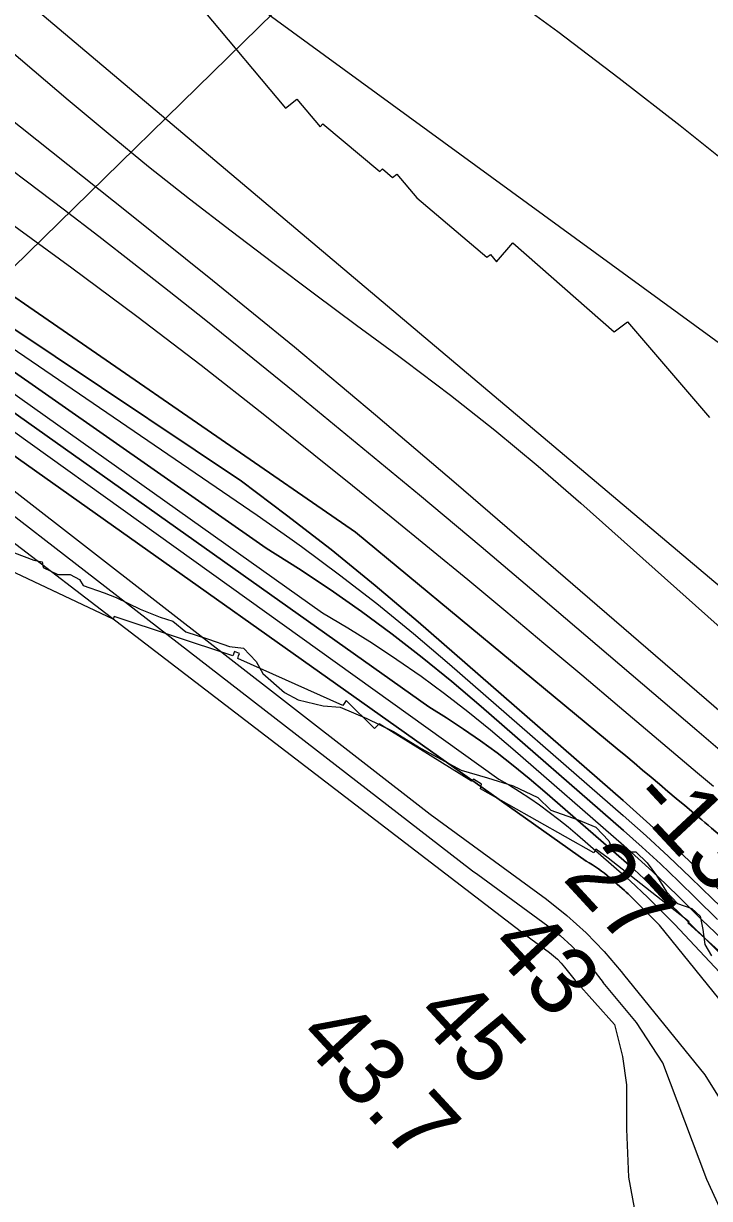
# Model space of a CAD drawing. Extents: x 3172231 to 3210228, y 940198 to 965780.
# Drawn here: x 3191420 to 3192098, y 946666 to 947827 of the extents above; entities that cross this region are included whole.
import ezdxf

# ---------------------------------------------------------------- set-up
doc = ezdxf.new("R2010")
doc.units = 0
for name, color, linetype in [('V-RIVR-EDGE', 7, 'Continuous'), ('V-RIVR-RANG', 7, 'Continuous'), ('V-RRAP-RVMT', 7, 'Continuous'), ('V-TOPO-DPTH', 7, 'Continuous'), ('V-TOPO-MAJR', 7, 'Continuous'), ('V-TOPO-MINR', 7, 'Continuous'), ('V-TOPO-WATR', 7, 'Continuous')]:
    doc.layers.add(name, color=color, linetype=linetype)

msp = doc.modelspace()

# ---------------------------------------------------------------- linework, layer by layer
at = {"layer": 'V-RIVR-EDGE'}
for points in [[(3191410.989, 947304.007), (3191430.16, 947296.699), (3191438.454, 947295.123), (3191439.477, 947289.415), (3191453.982, 947282.637), (3191465.91, 947282.608), (3191475.232, 947277.399), (3191478.848, 947271.685), (3191499.575, 947264.373), (3191511.492, 947259.676), (3191535.32, 947248.207), (3191555.009, 947240.379), (3191567.445, 947236.199), (3191580.385, 947225.795), (3191602.668, 947218.479), (3191623.395, 947211.167), (3191637.393, 947209.577)], [(3191637.393, 947209.577), (3191649.808, 947196.58), (3191656.521, 947184.635), (3191677.738, 947165.913), (3191691.204, 947158.619), (3191716.084, 947152.852), (3191732.676, 947151.255), (3191759.099, 947140.299), (3191785.516, 947127.268), (3191812.962, 947110.604), (3191852.324, 947089.243), (3191878.236, 947081.4), (3191903.629, 947073.558), (3191927.976, 947062.088), (3191940.911, 947049.609), (3191967.856, 947040.207), (3191985.471, 947032.903), (3191998.403, 947019.387), (3192001.494, 947011.081), (3192013.416, 947008.458), (3192024.826, 947008.43), (3192036.209, 946997.511), (3192045.513, 946985.041), (3192055.327, 946968.94), (3192066.19, 946957.503), (3192080.18, 946952.282), (3192088.46, 946945.001), (3192091.019, 946931.51), (3192093.058, 946916.984), (3192099.772, 946905.558)]]:
    msp.add_lwpolyline(points, dxfattribs=at)
at = {"layer": 'V-RIVR-RANG'}
msp.add_line((3190962.933, 947149.209), (3191771.579, 947939.938), dxfattribs=at)
at = {"layer": 'V-RRAP-RVMT'}
for p, q in [((3191598.117, 947839.368), (3191678.924, 947743.409)), ((3191678.924, 947743.409), (3191690.144, 947752.294)), ((3191690.144, 947752.294), (3191713.026, 947724.749)), ((3191713.026, 947724.749), (3191715.597, 947727.872)), ((3191715.597, 947727.872), (3191772.016, 947680.848)), ((3191772.016, 947680.848), (3191774.569, 947683.416)), ((3191774.569, 947683.416), (3191784.622, 947674.912)), ((3191784.622, 947674.912), (3191788.771, 947678.215)), ((3191788.771, 947678.215), (3191808.451, 947654.756)), ((3191808.451, 947654.756), (3191877.73, 947596.155)), ((3191887.379, 947591.567), (3191903.504, 947610.203)), ((3191903.504, 947610.203), (3192003.597, 947522.334)), ((3191877.73, 947596.155), (3191881.207, 947598.794)), ((3191881.207, 947598.794), (3191887.379, 947591.567)), ((3192003.597, 947522.334), (3192016.837, 947532.321)), ((3192016.837, 947532.321), (3192097.733, 947437.716)), ((3191508.358, 947238.465), (3191379.902, 947299.004)), ((3191509.476, 947241.033), (3191508.358, 947238.465)), ((3191626.634, 947202.077), (3191509.476, 947241.033)), ((3191628.502, 947206.514), (3191626.634, 947202.077)), ((3191633.347, 947204.462), (3191628.502, 947206.514)), ((3191631.761, 947199.489), (3191632.348, 947202.01)), ((3191632.348, 947202.01), (3191633.347, 947204.462)), ((3191735.368, 947152.878), (3191631.761, 947199.489)), ((3191738.606, 947157.933), (3191735.368, 947152.878)), ((3191766.795, 947130.142), (3191738.606, 947157.933)), ((3191771.263, 947134.875), (3191766.795, 947130.142)), ((3191862.56, 947078.107), (3191771.263, 947134.875)), ((3191864.608, 947080.065), (3191862.56, 947078.107)), ((3191872.512, 947075.175), (3191864.608, 947080.065)), ((3191871.574, 947070.704), (3191872.512, 947075.175)), ((3191983.551, 947007.435), (3191871.574, 947070.704)), ((3191985.541, 947010.895), (3191983.551, 947007.435)), ((3191997.753, 947002.147), (3191985.541, 947010.895)), ((3192077.492, 946939.273), (3191997.753, 947002.147)), ((3192076.467, 946938.134), (3192077.492, 946939.273)), ((3192142.85, 946878.104), (3192076.467, 946938.134))]:
    msp.add_line(p, q, dxfattribs=at)
at = {"layer": 'V-TOPO-DPTH'}
for points in [[(3190795.989, 948054.391), (3191058.755, 947768.507), (3191064.568, 947762.315), (3191070.468, 947756.208), (3191076.496, 947750.229), (3191082.61, 947744.334), (3191635.142, 947374.634), (3191679.916, 947341.25), (3191724.064, 947307.079), (3191767.273, 947271.729), (3191809.857, 947235.592), (3192012.278, 947059.062), (3192038.925, 947035.354), (3192065.252, 947011.301), (3192091.097, 946986.732), (3192116.621, 946961.819), (3192125.015, 946953.462)], [(3192125.015, 946953.462), (3192116.621, 946961.819), (3192091.097, 946986.732), (3192065.252, 947011.301), (3192038.925, 947035.354), (3192012.278, 947059.062), (3191809.857, 947235.592), (3191767.273, 947271.729), (3191724.064, 947307.079), (3191679.916, 947341.25), (3191635.142, 947374.634), (3191082.61, 947744.334), (3191076.496, 947750.229), (3191070.468, 947756.208), (3191064.568, 947762.315), (3191058.755, 947768.507), (3190795.989, 948054.391)], [(3192105.596, 946941.56), (3192084.673, 946962.391), (3192067.073, 946979.569), (3192049.253, 946996.51), (3192031.1, 947013.095), (3192012.726, 947029.442), (3191871.98, 947152.187), (3191843.196, 947176.588), (3191813.973, 947200.437), (3191784.094, 947223.457), (3191753.777, 947245.924), (3191722.828, 947267.51), (3191691.477, 947288.475), (3191659.523, 947308.509), (3191081.962, 947712.367), (3191066.909, 947726.551), (3191052.087, 947740.967), (3191037.61, 947755.73), (3191023.364, 947770.724), (3190904.893, 947898.407)], [(3190904.893, 947898.407), (3191023.364, 947770.724), (3191037.61, 947755.73), (3191052.087, 947740.967), (3191066.909, 947726.551), (3191081.962, 947712.367), (3191659.523, 947308.509), (3191691.477, 947288.475), (3191722.828, 947267.51), (3191753.777, 947245.924), (3191784.094, 947223.457), (3191813.973, 947200.437), (3191843.196, 947176.588), (3191871.98, 947152.187), (3192012.726, 947029.442), (3192031.1, 947013.095), (3192049.253, 946996.51), (3192067.073, 946979.569), (3192084.673, 946962.391), (3192105.596, 946941.56)], [(3192074.996, 946940.791), (3192052.727, 946962.962), (3192043.051, 946972.406), (3192033.254, 946981.719), (3192023.275, 946990.837), (3192013.173, 946999.824), (3191935.175, 947067.846), (3191919.66, 947080.985), (3191903.9, 947093.815), (3191887.774, 947106.182), (3191871.403, 947118.239), (3191854.676, 947129.792), (3191837.719, 947140.985), (3191820.416, 947151.636), (3191081.606, 947675.34), (3191055.894, 947699.044), (3191030.612, 947723.186), (3191005.973, 947747.984), (3190981.764, 947773.22), (3190956.043, 947800.747), (3190919.634, 947840.373)], [(3190919.634, 947840.373), (3190956.043, 947800.747), (3190981.764, 947773.22), (3191005.973, 947747.984), (3191030.612, 947723.186), (3191055.894, 947699.044), (3191081.606, 947675.34), (3191820.416, 947151.636), (3191837.719, 947140.985), (3191854.676, 947129.792), (3191871.403, 947118.239), (3191887.774, 947106.182), (3191903.9, 947093.815), (3191919.66, 947080.985), (3191935.175, 947067.846), (3192013.173, 946999.824), (3192023.275, 946990.837), (3192033.254, 946981.719), (3192043.051, 946972.406), (3192052.727, 946962.962), (3192074.996, 946940.791)], [(3191034.173, 947827.902), (3191041.949, 947819.8), (3191049.938, 947811.772), (3191058.11, 947803.943), (3191066.559, 947796.413), (3191075.192, 947789.082), (3191084.105, 947782.101), (3191748.04, 947324.383), (3192006.622, 947110.179), (3192014.989, 947103.225), (3192023.341, 947096.252), (3192031.67, 947089.253), (3192039.983, 947082.235), (3192048.29, 947075.208), (3192056.601, 947068.187), (3192064.921, 947061.176), (3192073.246, 947054.171), (3192086.789, 947042.788), (3192090.015, 947040.073), (3192093.24, 947037.357), (3192096.461, 947034.637), (3192099.681, 947031.915), (3192938.779, 946321.755)], [(3192938.779, 946321.755), (3192099.681, 947031.915), (3192096.461, 947034.637), (3192093.24, 947037.357), (3192090.015, 947040.073), (3192086.789, 947042.788), (3192073.246, 947054.171), (3192064.921, 947061.176), (3192056.601, 947068.187), (3192048.29, 947075.208), (3192039.983, 947082.235), (3192031.67, 947089.253), (3192023.341, 947096.252), (3192014.989, 947103.225), (3192006.622, 947110.179), (3191748.04, 947324.383), (3191084.105, 947782.101), (3191075.192, 947789.082), (3191066.559, 947796.413), (3191058.11, 947803.943), (3191049.938, 947811.772), (3191041.949, 947819.8), (3191034.173, 947827.902)], [(3192048.178, 946936.112), (3192044.493, 946939.925), (3192020.78, 946963.534), (3192017.256, 946966.929), (3192015.449, 946968.579), (3192013.621, 946970.205), (3191999.399, 946982.608), (3191996.644, 946984.938), (3191993.845, 946987.211), (3191990.978, 946989.399), (3191988.067, 946991.53), (3191985.089, 946993.567), (3191982.068, 946995.534), (3191978.982, 946997.397), (3191975.853, 946999.192), (3191057.366, 947650.198)], [(3191403.088, 947632.554), (3191467.814, 947585.565), (3191532.023, 947537.889), (3191595.454, 947489.184), (3191658.366, 947439.793), (3191706.871, 947401.077), (3191745.056, 947370.422), (3191783.125, 947339.626), (3191821.021, 947308.616), (3191858.802, 947277.465), (3191896.449, 947246.151), (3191934.033, 947214.763), (3191971.524, 947183.262), (3192008.952, 947151.688), (3192085.816, 947086.649), (3192101.652, 947073.241)], [(3191403.088, 947632.554), (3191467.814, 947585.565), (3191532.023, 947537.889), (3191595.454, 947489.184), (3191658.366, 947439.793), (3191706.871, 947401.077), (3191745.056, 947370.422), (3191783.125, 947339.626), (3191821.021, 947308.616), (3191858.802, 947277.465), (3191896.449, 947246.151), (3191934.033, 947214.763), (3191971.524, 947183.262), (3192008.952, 947151.688), (3192085.816, 947086.649), (3192101.652, 947073.241)], [(3192454.597, 945730.763), (3192433.513, 945838.931), (3192413.857, 945970.211), (3192408.07, 946075.617), (3192400.398, 946242.672), (3192384.69, 946358.038), (3192366.954, 946449.543), (3192323.384, 946543.08), (3192273.844, 946632.65), (3192148.926, 946811.832), (3192048.178, 946936.112)], [(3192556.965, 945873.249), (3192535.012, 945918.306), (3192525.143, 945960.083), (3192529.261, 946045.586), (3192539.308, 946111.193), (3192553.314, 946166.851), (3192559.38, 946228.487), (3192561.44, 946272.233), (3192559.519, 946312.008), (3192553.616, 946347.813), (3192527.864, 946399.56), (3192508.058, 946441.353), (3192448.554, 946515.031), (3192238.314, 946779.866), (3192074.996, 946940.791)], [(3192074.996, 946940.791), (3192238.314, 946779.866), (3192448.554, 946515.031), (3192508.058, 946441.353), (3192527.864, 946399.56), (3192553.616, 946347.813), (3192559.519, 946312.008), (3192561.44, 946272.233), (3192559.38, 946228.487), (3192553.314, 946166.851), (3192539.308, 946111.193), (3192529.261, 946045.586), (3192525.143, 945960.083), (3192535.012, 945918.306), (3192556.965, 945873.249)]]:
    msp.add_lwpolyline(points, dxfattribs=at)
at = {"layer": 'V-TOPO-MAJR'}
for points in [[(3190780.826, 947870.291), (3190841.33, 947802.226), (3190925.193, 947708.779), (3190944.226, 947687.848), (3190963.438, 947667.086), (3190982.921, 947646.576), (3191002.583, 947626.236), (3191916.297, 946926.02), (3191939.622, 946908.908), (3191943.668, 946905.677), (3191947.52, 946902.246), (3191951.081, 946898.512), (3191954.447, 946894.578), (3191965.03, 946881.133)], [(3192112.75, 947104.696), (3192085.094, 947128.316), (3191933.046, 947258.17), (3191872.227, 947309.714), (3191811.151, 947360.95), (3191749.689, 947411.721), (3191687.97, 947462.184), (3191632.721, 947507.009), (3191598.329, 947534.696), (3191563.798, 947562.207), (3191529.059, 947589.454), (3191494.182, 947616.526), (3191459.126, 947643.368), (3191423.974, 947670.082), (3191388.674, 947696.601), (3191353.277, 947722.992), (3191239.467, 947807.355), (3191211.089, 947828.544)], [(3191965.03, 946881.133), (3192003.878, 946837.926), (3192011.775, 946806.095), (3192015.704, 946778.248), (3192015.631, 946734.499), (3192017.539, 946686.769), (3192043.148, 946549.513), (3192070.782, 946434.128), (3192118.261, 946300.812), (3192181.541, 946107.812), (3192282.525, 945878.955), (3192347.711, 945691.839)]]:
    msp.add_lwpolyline(points, dxfattribs=at)
at = {"layer": 'V-TOPO-MINR'}
for points in [[(3189654.756, 949405.366), (3190276.246, 948537.001), (3190281.623, 948529.611), (3190287.075, 948522.279), (3190292.642, 948515.033), (3190298.284, 948507.844), (3190380.452, 948404.824), (3190427.618, 948346.486), (3190475.293, 948288.575), (3190523.733, 948231.301), (3190572.682, 948174.452), (3190982.548, 947704.784), (3190988.103, 947698.499), (3190993.711, 947692.263), (3190999.397, 947686.099), (3191005.137, 947679.982), (3191821.886, 947045.773), (3191936.602, 946961.604), (3191956.768, 946945.504), (3191975.964, 946928.401), (3191993.708, 946909.795), (3192010.483, 946890.186), (3192012.814, 946887.224)], [(3190795.989, 948054.391), (3191058.755, 947768.507), (3191064.568, 947762.315), (3191070.468, 947756.208), (3191076.496, 947750.229), (3191082.61, 947744.334), (3191635.142, 947374.634), (3191679.916, 947341.25), (3191724.064, 947307.079), (3191767.273, 947271.729), (3191809.857, 947235.592), (3192012.278, 947059.062), (3192038.925, 947035.354), (3192065.252, 947011.301), (3192091.097, 946986.732), (3192116.621, 946961.819), (3192125.015, 946953.462)], [(3192347.015, 947336.056), (3191437.622, 947999.666)], [(3190880.337, 947944.43), (3191041.855, 947769.581), (3191051.689, 947759.172), (3191061.675, 947748.915), (3191071.889, 947738.884), (3191082.254, 947729.005), (3191650.711, 947341.141), (3191683.208, 947318.366), (3191694.589, 947310.147), (3191732.069, 947282.287), (3191769.016, 947253.755), (3191805.164, 947224.218), (3191840.779, 947194.01), (3192012.502, 947044.249), (3192035.012, 947024.222), (3192057.251, 947003.904), (3192079.083, 946983.15), (3192100.643, 946962.105), (3192107.839, 946954.941)], [(3190769.795, 947916.905), (3190955.962, 947706.712), (3190967.744, 947693.583), (3190979.637, 947680.557), (3190991.699, 947667.687), (3191003.873, 947654.92), (3191863.674, 946989.558), (3191868.763, 946986.139), (3191938.112, 946935.255), (3191950.218, 946925.59), (3191961.742, 946915.323), (3191972.393, 946904.153), (3191982.463, 946892.382), (3191992.769, 946879.29)], [(3190904.893, 947898.407), (3191023.364, 947770.724), (3191037.61, 947755.73), (3191052.087, 947740.967), (3191066.909, 947726.551), (3191081.962, 947712.367), (3191659.523, 947308.509), (3191691.477, 947288.475), (3191722.828, 947267.51), (3191753.777, 947245.924), (3191784.094, 947223.457), (3191813.973, 947200.437), (3191843.196, 947176.588), (3191871.98, 947152.187), (3192012.726, 947029.442), (3192031.1, 947013.095), (3192049.253, 946996.51), (3192067.073, 946979.569), (3192084.673, 946962.391), (3192105.596, 946941.56)], [(3191313.374, 947879.998), (3191463.893, 947751.654), (3191503.511, 947718.45), (3191543.496, 947685.703), (3191584.032, 947653.64), (3191624.936, 947622.034), (3191666.188, 947590.868), (3191707.535, 947559.83), (3191749.028, 947528.986), (3191790.617, 947498.27), (3191797.26, 947493.388), (3191841.742, 947459.711), (3191885.559, 947425.213), (3191928.377, 947389.482), (3191970.529, 947352.931), (3192178.808, 947167.071)], [(3191237.421, 947864.246), (3191285.532, 947826.414), (3191298, 947816.68), (3191310.513, 947807.003), (3191323.092, 947797.414), (3191335.716, 947787.882), (3191348.335, 947778.344), (3191360.902, 947768.738), (3191373.39, 947759.031), (3191385.827, 947749.256), (3191525.002, 947638.957), (3191606.573, 947573.482), (3191687.593, 947507.339), (3191767.786, 947440.196), (3191847.426, 947372.385), (3192135.776, 947123.763)], [(3192185.63, 947632.443), (3192068.722, 947725.721), (3192008.581, 947772.715), (3191947.823, 947818.879), (3191886.14, 947863.799)], [(3190930.078, 947850.58), (3191003.325, 947771.936), (3191022.365, 947751.998), (3191041.728, 947732.386), (3191061.574, 947713.264), (3191081.742, 947694.468), (3191715.374, 947244.512), (3191740.266, 947229.738), (3191764.84, 947214.47), (3191788.937, 947198.459), (3191812.715, 947181.953), (3191835.998, 947164.751), (3191858.94, 947147.118), (3191881.368, 947128.836), (3191903.455, 947110.123), (3192012.949, 947014.633), (3192027.187, 947001.966), (3192041.254, 946989.115), (3192055.063, 946975.988), (3192068.701, 946962.676), (3192090.281, 946941.191)], [(3191423.567, 947848.409), (3192230.35, 947167.61)], [(3191034.173, 947827.902), (3191041.949, 947819.8), (3191049.938, 947811.772), (3191058.11, 947803.943), (3191066.559, 947796.413), (3191075.192, 947789.082), (3191084.105, 947782.101), (3191748.04, 947324.383), (3192006.622, 947110.179), (3192014.989, 947103.225), (3192023.341, 947096.252), (3192031.67, 947089.253), (3192039.983, 947082.235), (3192048.29, 947075.208), (3192056.601, 947068.187), (3192064.921, 947061.176), (3192073.246, 947054.171), (3192086.789, 947042.788), (3192090.015, 947040.073), (3192093.24, 947037.357), (3192096.461, 947034.637), (3192099.681, 947031.915), (3192938.779, 946321.755)], [(3191055.119, 947678.48), (3191889.718, 947080.147), (3191899.995, 947074.184), (3191910.133, 947068.002), (3191920.063, 947061.492), (3191929.855, 947054.762), (3191939.434, 947047.73), (3191948.868, 947040.513), (3191958.083, 947033.021), (3191967.154, 947025.344), (3192013.397, 946985.012), (3192019.361, 946979.706), (3192025.254, 946974.323), (3192031.038, 946968.824), (3192036.751, 946963.248), (3192063.442, 946936.674)], [(3191057.366, 947650.198), (3191975.853, 946999.192), (3191978.982, 946997.397), (3191982.068, 946995.534), (3191985.089, 946993.567), (3191988.067, 946991.53), (3191990.978, 946989.399), (3191993.845, 946987.211), (3191996.644, 946984.938), (3191999.399, 946982.608), (3192013.621, 946970.205), (3192015.449, 946968.579), (3192017.256, 946966.929), (3192020.78, 946963.534), (3192044.493, 946939.925), (3192048.178, 946936.112)], [(3191403.088, 947632.554), (3191467.814, 947585.565), (3191532.023, 947537.889), (3191595.454, 947489.184), (3191658.366, 947439.793), (3191706.871, 947401.077), (3191745.056, 947370.422), (3191783.125, 947339.626), (3191821.021, 947308.616), (3191858.802, 947277.465), (3191896.449, 947246.151), (3191934.033, 947214.763), (3191971.524, 947183.262), (3192008.952, 947151.688), (3192085.816, 947086.649), (3192101.652, 947073.241)], [(3192454.597, 945730.763), (3192433.513, 945838.931), (3192413.857, 945970.211), (3192408.07, 946075.617), (3192400.398, 946242.672), (3192384.69, 946358.038), (3192366.954, 946449.543), (3192323.384, 946543.08), (3192273.844, 946632.65), (3192148.926, 946811.832), (3192048.178, 946936.112)], [(3192492.143, 945790.417), (3192485.226, 945860.719), (3192481.334, 945910.441), (3192481.45, 945980.042), (3192479.629, 946079.475), (3192479.821, 946194.814), (3192470.026, 946280.34), (3192460.174, 946332.06), (3192430.533, 946435.517), (3192375.097, 946564.868), (3192331.48, 946630.565), (3192256.119, 946730.121), (3192176.759, 946815.763), (3192063.442, 946936.674)], [(3192567.388, 945896.273), (3192554.927, 945942.136), (3192551.038, 945993.846), (3192557.104, 946055.482), (3192577.062, 946105.164), (3192589.06, 946148.894), (3192597.08, 946190.641), (3192599.141, 946234.387), (3192599.214, 946278.136), (3192597.336, 946343.763), (3192583.472, 946373.615), (3192559.691, 946415.415), (3192490.299, 946518.938), (3192303.833, 946737.996), (3192090.281, 946941.191)], [(3192384.031, 945691.507), (3192369.742, 945737.618), (3192326.265, 945886.836), (3192278.809, 946034.072), (3192219.587, 946276.78), (3192190.019, 946423.986), (3192142.579, 946581.165), (3192095.05, 946684.652), (3192051.516, 946800.063), (3192025.744, 946839.878), (3191992.769, 946879.29)], [(3192012.814, 946887.224), (3192093.235, 946788.062), (3192176.49, 946654.687), (3192251.812, 946531.268), (3192301.315, 946419.823), (3192324.98, 946308.422), (3192340.702, 946201.011), (3192360.329, 946051.833), (3192370.137, 945974.261), (3192387.866, 945878.779), (3192399.652, 945795.238), (3192413.455, 945729.591), (3192423.115, 945691.168)]]:
    msp.add_lwpolyline(points, dxfattribs=at)
at = {"layer": 'V-TOPO-WATR'}
for points in [[(3190919.634, 947840.373), (3190956.043, 947800.747), (3190981.764, 947773.22), (3191005.973, 947747.984), (3191030.612, 947723.186), (3191055.894, 947699.044), (3191081.606, 947675.34), (3191820.416, 947151.636), (3191837.719, 947140.985), (3191854.676, 947129.792), (3191871.403, 947118.239), (3191887.774, 947106.182), (3191903.9, 947093.815), (3191919.66, 947080.985), (3191935.175, 947067.846), (3192013.173, 946999.824), (3192023.275, 946990.837), (3192033.254, 946981.719), (3192043.051, 946972.406), (3192052.727, 946962.962), (3192074.996, 946940.791)], [(3192556.965, 945873.249), (3192535.012, 945918.306), (3192525.143, 945960.083), (3192529.261, 946045.586), (3192539.308, 946111.193), (3192553.314, 946166.851), (3192559.38, 946228.487), (3192561.44, 946272.233), (3192559.519, 946312.008), (3192553.616, 946347.813), (3192527.864, 946399.56), (3192508.058, 946441.353), (3192448.554, 946515.031), (3192238.314, 946779.866), (3192074.996, 946940.791)]]:
    msp.add_lwpolyline(points, dxfattribs=at)

# ---------------------------------------------------------------- texts
at = {"layer": 'V-RIVR-RANG'}
for s, rotation, p in [('-13', 312.955556, (3192016.346, 947058.421)), ('27', 312.688326, (3191951.535, 946981.66)), ('43', 312.688326, (3191878.193, 946913.682)), ('45', 312.688326, (3191804.852, 946845.704)), ('43.7', 312.688326, (3191688.587, 946824.26))]:
    msp.add_text(s, height=67, rotation=rotation, dxfattribs=at).set_placement(p)

doc.saveas('drawing.dxf')
